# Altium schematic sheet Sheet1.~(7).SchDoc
size A4
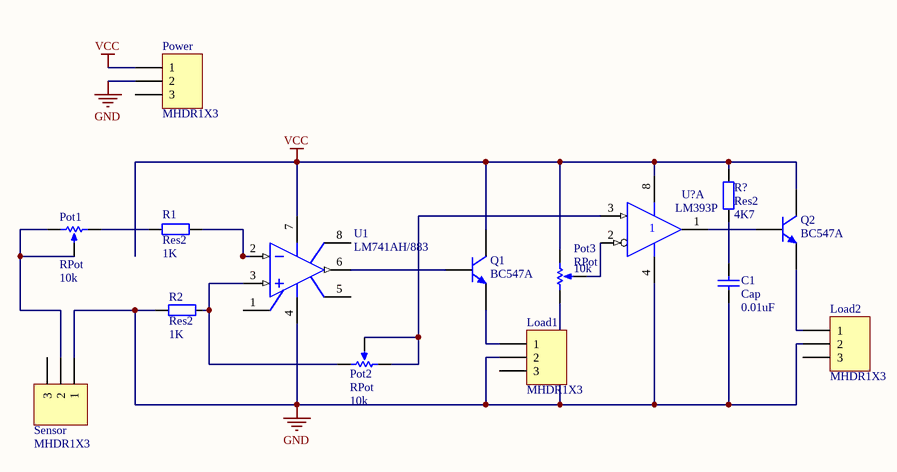
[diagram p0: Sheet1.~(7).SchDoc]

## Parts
C1  Cap  value 0.01uF  [RAD-0.3]
Load1  MHDR1X3  [MHDR1X3]
Load2  MHDR1X3  [MHDR1X3]
Pot1  RPot  value 10k  [VR5]
Pot2  RPot  value 10k  [VR5]
Pot3  RPot  value 10k  [VR5]
Power  MHDR1X3  [MHDR1X3]
Q1  BC547A  [SOT54]
Q2  BC547A  [SOT54]
R1  Res2  value 1K  [AXIAL-0.4]
R2  Res2  value 1K  [AXIAL-0.4]
R?  Res2  value 4K7  [AXIAL-0.4]
Sensor  MHDR1X3  [MHDR1X3]
U1  LM741AH/883  [H08C]
U?  LM393P  [P008]  (part A of 2)

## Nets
GND: C1.1 Load1.2 Load2.2 Pot3.1(TOP) Power.2 R2.1 Sensor.1 U1.4(V-) U?.4(GND)
VCC: Pot3.2(BOT) Power.1 Q1.3(C) Q2.3(C) R?.2 U1.7(V+) U?.8(VCC)
NetC1_2: C1.2 R?.1
NetLoad1_1: Load1.1 Q1.1(E)
NetLoad2_1: Load2.1 Q2.1(E)
NetPot1_1: Pot1.1(TOP) Pot1.3(TAP) Sensor.2
NetPot1_2: Pot1.2(BOT) R1.1
NetPot2_1: Pot2.1(TOP) Pot2.3(TAP) U?.3(IN+)
NetPot2_2: Pot2.2(BOT) R2.2 U1.3(IN+)
NetPot3_3: Pot3.3(TAP) U?.2(IN-)
NetQ1_2: Q1.2(B) U1.6(OUT)
NetQ2_2: Q2.2(B) U?.1(OUT)
NetR1_2: R1.2 U1.2(IN-)

Not connected (* = marked no-connect by the designer): Load1 3; Load2 3; Power 3; Sensor 3; U1 1(OS_NULL) 5(OS_NULL) 8(NC)

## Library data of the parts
C1 = Cap: Capacitor
Load1 Load2 Power Sensor = MHDR1X3: Header, 3-Pin
Pot1-Pot3 = RPot: Potentiometer; Sim Note: Enter the Resistance value and the set point into parameter fields.; Set Position: 0.5
Q1 Q2 = BC547A: NPN General-purpose Transistor
R1 R2 R? = Res2: Resistor
U1 = LM741AH/883: Operational Amplifier; ComponentAvailability: Obsolete
U? = LM393P: Dual Differential Comparator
